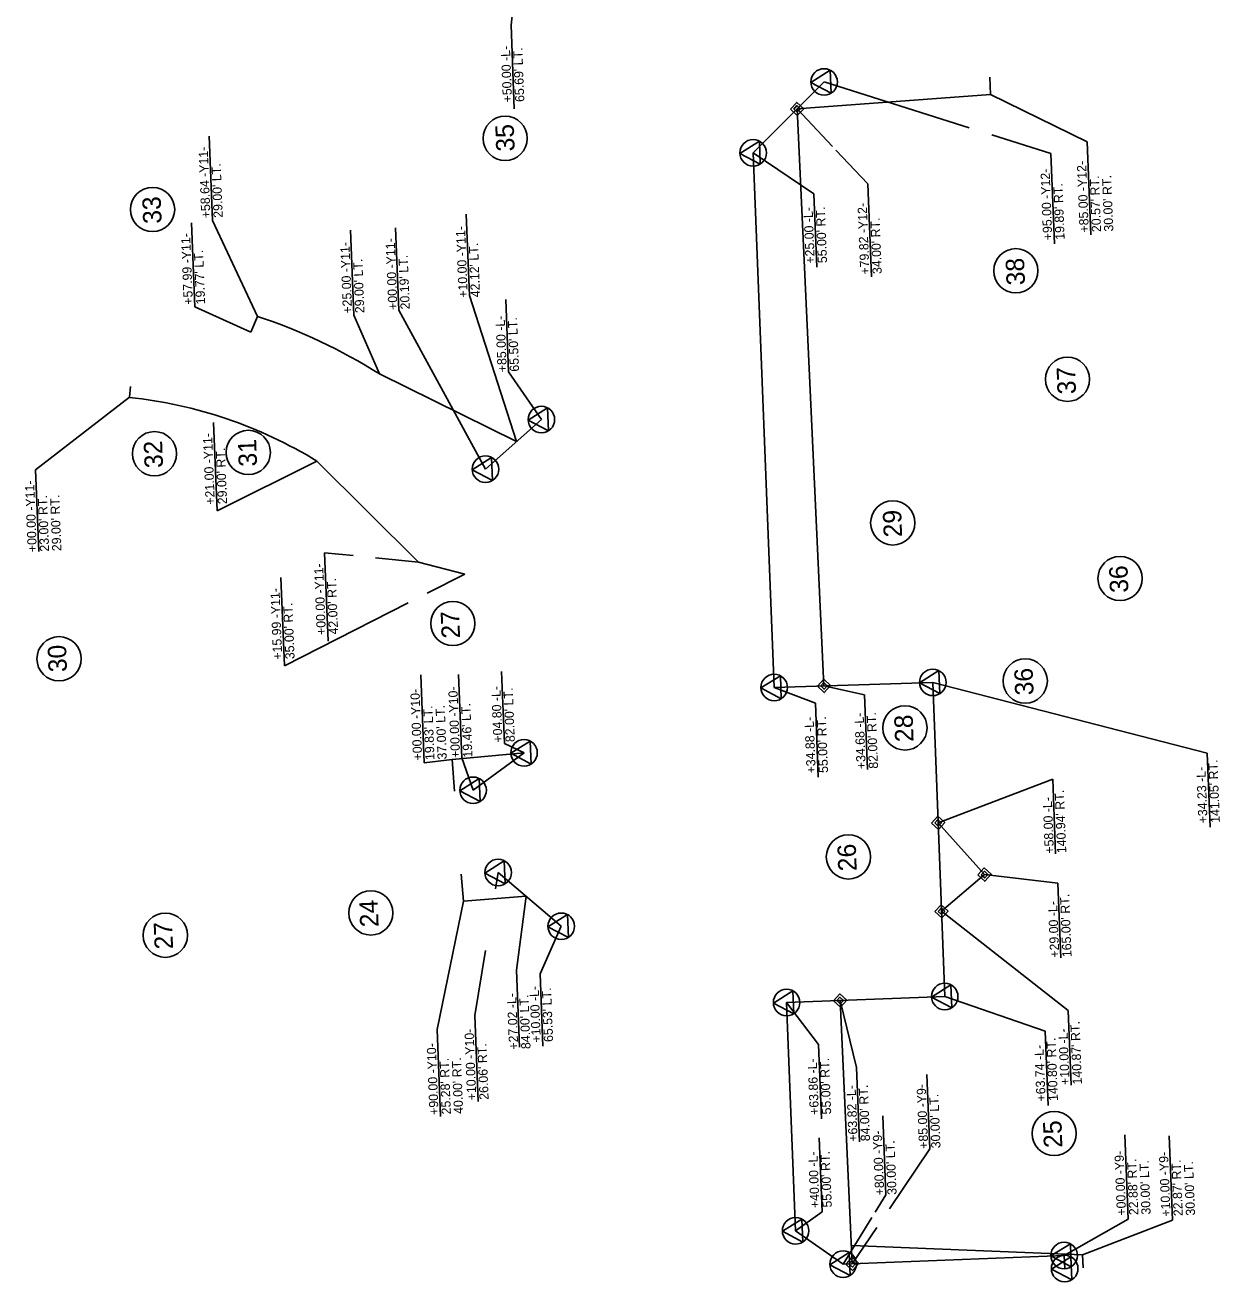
# Model space of a CAD drawing. Extents: x 1627970 to 1628801, y 761752 to 765698.
# Drawn here: x 1628052 to 1628700, y 763889 to 764570 of the extents above; entities that cross this region are included whole.
import ezdxf

# ---------------------------------------------------------------- set-up
doc = ezdxf.new("R2010")
doc.units = 0
for name, color, linetype in [('Exist Property Line Leader', 7, 'Continuous'), ('Exist Property Line Text', 7, 'Continuous'), ('Exist Right of Way Control of Access Line', 7, 'Continuous'), ('Exist Right of Way Easement Line', 7, 'Continuous'), ('Exist Right of Way Monument Leader', 7, 'Continuous'), ('Exist Right of Way Monument Text', 7, 'Continuous'), ('Exist Roads EOT', 7, 'Continuous'), ('Exist Structure Major Deck Tunnel Box Culvert', 7, 'Continuous'), ('Exist Utilities Gas UG Line', 7, 'Continuous'), ('Exist Utilities Gas UG Line Text', 7, 'Continuous'), ('Exist Utilities Other Unknown UG SUE Text', 7, 'Continuous')]:
    doc.layers.add(name, color=color, linetype=linetype)

msp = doc.modelspace()

# ---------------------------------------------------------------- linework, layer by layer
at = {"layer": 'Exist Property Line Leader'}
msp.add_line((1628485.1, 764211.71), (1628470.48, 764524.56), dxfattribs=at)
msp.add_lwpolyline([(1628500.46, 763898.28), (1628493.83, 764041.07)], dxfattribs=at)
at = {"layer": 'Exist Property Line Text'}
for p, q in [((1628312.16, 764508.63), (1628312.16, 764508.63)), ((1628120.93, 764470.04), (1628120.93, 764470.04)), ((1628589.14, 764436.82), (1628589.14, 764436.82)), ((1628617.17, 764377.95), (1628617.17, 764377.95)), ((1628121.94, 764337.62), (1628121.94, 764337.62)), ((1628172.84, 764338.31), (1628172.84, 764338.31)), ((1628522.41, 764300.08), (1628522.41, 764300.08)), ((1628645.68, 764269.95), (1628645.68, 764269.95)), ((1628283.79, 764245.53), (1628283.79, 764245.53)), ((1628070.17, 764226.39), (1628070.17, 764226.39)), ((1628594.27, 764214.35), (1628594.27, 764214.35)), ((1628529.03, 764188.89), (1628529.03, 764188.89)), ((1628498.34, 764118.97), (1628498.34, 764118.97)), ((1628239.29, 764088.56), (1628239.29, 764088.56)), ((1628127.83, 764076.46), (1628127.83, 764076.46)), ((1628609.95, 763968.94), (1628609.95, 763968.94))]:
    msp.add_line(p, q, dxfattribs=at)
for centre in [(1628312.16, 764508.63), (1628120.93, 764470.04), (1628589.14, 764436.82), (1628617.17, 764377.95), (1628121.94, 764337.62), (1628172.84, 764338.31), (1628522.41, 764300.08), (1628645.68, 764269.95), (1628283.79, 764245.53), (1628070.17, 764226.39), (1628594.27, 764214.35), (1628529.03, 764188.89), (1628498.34, 764118.97), (1628239.29, 764088.56), (1628127.83, 764076.46), (1628609.95, 763968.94)]:
    msp.add_circle(centre, 12, dxfattribs=at)
at = {"layer": 'Exist Right of Way Control of Access Line'}
for p, q in [((1628446.68, 764500.75), (1628485.14, 764539.21)), ((1628458.11, 764210.85), (1628446.68, 764500.75)), ((1628301.47, 764329.22), (1628331.79, 764356.11)), ((1628544.12, 764213.6), (1628458.11, 764210.85)), ((1628550.59, 764043.22), (1628544.12, 764213.6)), ((1628294.76, 764155.07), (1628322.4, 764175.4)), ((1628342.59, 764081.32), (1628308.34, 764110.49)), ((1628464.85, 764039.97), (1628550.59, 764043.22)), ((1628469.73, 763916.2), (1628464.85, 764039.97)), ((1628495.46, 763898.08), (1628469.73, 763916.2)), ((1628615.37, 763902.81), (1628495.46, 763898.08)), ((1628615.65, 763895.7), (1628615.37, 763902.81))]:
    msp.add_line(p, q, dxfattribs=at)
at = {"layer": 'Exist Right of Way Easement Line'}
for p, q in [((1628609.15, 764161.03), (1628547.01, 764137.42)), ((1628609.15, 764161.03), (1628610.75, 764120.61)), ((1628612.02, 764104.64), (1628572.2, 764109.39)), ((1628612.02, 764104.64), (1628613.62, 764064.21)), ((1628617.63, 764035.59), (1628548.84, 764089.45)), ((1628617.63, 764035.59), (1628619.23, 763995.17))]:
    msp.add_line(p, q, dxfattribs=at)
at = {"layer": 'Exist Right of Way Monument Leader'}
for points in [[(1628466.89, 764524.41), (1628470.34, 764528.15), (1628474.08, 764524.7), (1628470.63, 764520.96)], [(1628468.69, 764524.49), (1628470.41, 764526.36), (1628472.28, 764524.63), (1628470.56, 764522.76)], [(1628481.5, 764211.57), (1628484.96, 764215.31), (1628488.69, 764211.85), (1628485.24, 764208.11)], [(1628483.3, 764211.64), (1628485.03, 764213.51), (1628486.9, 764211.78), (1628485.17, 764209.91)], [(1628543.42, 764137.28), (1628546.87, 764141.02), (1628550.61, 764137.56), (1628547.16, 764133.82)], [(1628545.21, 764137.35), (1628546.94, 764139.22), (1628548.81, 764137.49), (1628547.08, 764135.62)], [(1628568.6, 764109.25), (1628572.06, 764112.99), (1628575.79, 764109.53), (1628572.34, 764105.79)], [(1628570.4, 764109.32), (1628572.13, 764111.19), (1628574, 764109.46), (1628572.27, 764107.59)], [(1628545.24, 764089.31), (1628548.69, 764093.05), (1628552.43, 764089.6), (1628548.98, 764085.86)], [(1628547.04, 764089.38), (1628548.77, 764091.25), (1628550.63, 764089.52), (1628548.91, 764087.65)], [(1628490.23, 764040.93), (1628493.69, 764044.66), (1628497.43, 764041.21), (1628493.97, 764037.47)], [(1628492.03, 764041), (1628493.76, 764042.87), (1628495.63, 764041.14), (1628493.9, 764039.27)], [(1628496.86, 763898.14), (1628500.32, 763901.88), (1628504.06, 763898.42), (1628500.6, 763894.68)], [(1628498.66, 763898.21), (1628500.39, 763900.08), (1628502.26, 763898.35), (1628500.53, 763896.48)]]:
    msp.add_lwpolyline(points, close=True, dxfattribs=at)
at = {"layer": 'Exist Right of Way Monument Text'}
for p, q in [((1628575.45, 764532.4), (1628575.1, 764541.83)), ((1628470.48, 764524.56), (1628575.45, 764532.4)), ((1628174.24, 764403.55), (1628177.81, 764412.1)), ((1628108.37, 764368.18), (1628109.01, 764374.14)), ((1628243.98, 764380.84), (1628318.33, 764344.17)), ((1628265.07, 764278.8), (1628210.03, 764333.65)), ((1628290.22, 764272.29), (1628265.07, 764278.8)), ((1628283.41, 764171.76), (1628322.4, 764175.4)), ((1628284.77, 764154.64), (1628283.41, 764171.76)), ((1628289.51, 764095), (1628288.34, 764109.68)), ((1628323.47, 764097.6), (1628289.51, 764095)), ((1628625.36, 763903.21), (1628500.13, 763908.27)), ((1628625.64, 763896.08), (1628625.36, 763903.21))]:
    msp.add_line(p, q, dxfattribs=at)
for radius, start, end in [(304, 57.80151, 71.62829), (246, 58.63491, 83.84505)]:
    msp.add_arc((1628081.99, 764123.59), radius, start, end, dxfattribs=at)
at = {"layer": 'Exist Roads EOT'}
for p, q in [((1628470.48, 764524.56), (1628489.77, 764504.12)), ((1628491.57, 764502.22), (1628508.86, 764483.9)), ((1628510.91, 764433.58), (1628508.86, 764483.9)), ((1628507.04, 764206.85), (1628485.1, 764211.71)), ((1628507.04, 764206.85), (1628508.63, 764166.42)), ((1628502.69, 764004.82), (1628493.83, 764041.07)), ((1628502.69, 764004.82), (1628504.28, 763964.4)), ((1628540.92, 764000.99), (1628542.52, 763960.56)), ((1628542.52, 763960.56), (1628520.61, 763928.12)), ((1628513.81, 763918.05), (1628500.46, 763898.28))]:
    msp.add_line(p, q, dxfattribs=at)
at = {"layer": 'Exist Structure Major Deck Tunnel Box Culvert'}
for p, q in [((1628572.2, 764109.39), (1628547.01, 764137.42)), ((1628548.84, 764089.45), (1628572.2, 764109.39))]:
    msp.add_line(p, q, dxfattribs=at)
at = {"layer": 'Exist Utilities Gas UG Line'}
for p, q in [((1628563.83, 764514.39), (1628485.14, 764539.21)), ((1628608.16, 764500.41), (1628576.16, 764510.51)), ((1628479.67, 764478.5), (1628446.68, 764500.75)), ((1628608.16, 764500.41), (1628610.09, 764451.41)), ((1628479.67, 764478.5), (1628481.24, 764438.72)), ((1628252.75, 764460.05), (1628254.51, 764415.5)), ((1628301.47, 764329.22), (1628254.51, 764415.5)), ((1628312.46, 764421.25), (1628314, 764382.03)), ((1628331.79, 764356.11), (1628314, 764382.03)), ((1628286.84, 764217.92), (1628288.63, 764172.7)), ((1628310.22, 764219.41), (1628311.76, 764180.38)), ((1628458.11, 764210.85), (1628480.44, 764202.37)), ((1628544.12, 764213.6), (1628692.97, 764175.3)), ((1628480.44, 764202.37), (1628482.03, 764162.11)), ((1628311.76, 764180.38), (1628322.4, 764175.4)), ((1628288.63, 764172.7), (1628294.76, 764155.07)), ((1628692.97, 764175.3), (1628694.56, 764135.05)), ((1628306.92, 764101.71), (1628308.34, 764110.49)), ((1628331.1, 764055.62), (1628342.59, 764081.32)), ((1628295.73, 764032.92), (1628301.47, 764068.22)), ((1628331.1, 764055.62), (1628332.65, 764016.34)), ((1628550.59, 764043.22), (1628605.14, 764024.48)), ((1628464.85, 764039.97), (1628482.14, 764017.19)), ((1628295.73, 764032.92), (1628297.56, 763986.39)), ((1628605.14, 764024.48), (1628606.72, 763984.22)), ((1628482.14, 764017.19), (1628483.72, 763976.93)), ((1628517.03, 763978.6), (1628518.73, 763935.61)), ((1628482.48, 763966.67), (1628484.07, 763926.42)), ((1628648.29, 763968.19), (1628650.09, 763922.47)), ((1628512.95, 763926.3), (1628518.73, 763935.61)), ((1628469.73, 763916.2), (1628484.07, 763926.42)), ((1628495.46, 763898.08), (1628511.11, 763923.33)), ((1628615.37, 763902.81), (1628650.09, 763922.47))]:
    msp.add_line(p, q, dxfattribs=at)
at = {"layer": 'Exist Utilities Gas UG Line Text'}
for p, q in [((1628321.16, 764620.9), (1628315.34, 764569.97)), ((1628315.34, 764569.97), (1628317.12, 764524.69)), ((1628575.45, 764532.4), (1628627.83, 764506.65)), ((1628151.62, 764509.81), (1628153.42, 764464.15)), ((1628629.88, 764456.34), (1628627.83, 764506.65)), ((1628142.09, 764462.89), (1628143.89, 764417.23)), ((1628177.81, 764412.1), (1628153.42, 764464.15)), ((1628291.01, 764467.44), (1628292.74, 764423.41)), ((1628228.26, 764458.83), (1628230.08, 764412.76)), ((1628292.74, 764423.41), (1628318.33, 764344.17)), ((1628174.24, 764403.55), (1628143.89, 764417.23)), ((1628243.98, 764380.84), (1628230.08, 764412.76)), ((1628108.37, 764368.18), (1628057.44, 764328.89)), ((1628153.97, 764354.62), (1628155.86, 764306.66)), ((1628210.03, 764333.65), (1628155.86, 764306.66)), ((1628057.44, 764328.89), (1628059.18, 764284.59)), ((1628214.22, 764283.9), (1628216.11, 764236)), ((1628229.65, 764282.35), (1628214.22, 764283.9)), ((1628265.07, 764278.8), (1628241.87, 764281.13)), ((1628290.22, 764272.29), (1628269.77, 764261.92)), ((1628190.56, 764270.56), (1628192.45, 764222.66)), ((1628259.59, 764256.75), (1628192.45, 764222.66)), ((1628266.39, 764217.77), (1628268.27, 764170.03)), ((1628268.27, 764170.03), (1628283.41, 764171.76)), ((1628275.32, 764025.35), (1628289.51, 764095)), ((1628318.25, 764057.51), (1628323.47, 764097.6)), ((1628318.25, 764057.51), (1628319.89, 764015.78)), ((1628275.32, 764025.35), (1628277.17, 763978.26)), ((1628672.41, 763967.66), (1628674.21, 763921.94)), ((1628625.36, 763903.21), (1628674.21, 763921.94))]:
    msp.add_line(p, q, dxfattribs=at)
at = {"layer": 'Exist Utilities Other Unknown UG SUE Text'}
for p, q in [((1628485.14, 764539.21), (1628485.14, 764539.21)), ((1628470.48, 764524.56), (1628470.48, 764524.56)), ((1628446.68, 764500.75), (1628446.68, 764500.75)), ((1628331.79, 764356.11), (1628331.79, 764356.11)), ((1628301.47, 764329.22), (1628301.47, 764329.22)), ((1628458.11, 764210.85), (1628458.11, 764210.85)), ((1628485.1, 764211.71), (1628485.1, 764211.71)), ((1628544.12, 764213.6), (1628544.12, 764213.6)), ((1628322.4, 764175.4), (1628322.4, 764175.4)), ((1628294.76, 764155.07), (1628294.76, 764155.07)), ((1628547.01, 764137.42), (1628547.01, 764137.42)), ((1628308.34, 764110.49), (1628308.34, 764110.49)), ((1628572.2, 764109.39), (1628572.2, 764109.39)), ((1628548.84, 764089.45), (1628548.84, 764089.45)), ((1628342.59, 764081.32), (1628342.59, 764081.32)), ((1628493.83, 764041.07), (1628493.83, 764041.07)), ((1628550.59, 764043.22), (1628550.59, 764043.22)), ((1628464.85, 764039.97), (1628464.85, 764039.97)), ((1628469.73, 763916.2), (1628469.73, 763916.2)), ((1628495.46, 763898.08), (1628495.46, 763898.08)), ((1628500.46, 763898.28), (1628500.46, 763898.28)), ((1628615.37, 763902.81), (1628615.37, 763902.81)), ((1628615.65, 763895.7), (1628615.65, 763895.7))]:
    msp.add_line(p, q, dxfattribs=at)
for points in [[(1628477.93, 764538.94), (1628488.5, 764545.58), (1628488.99, 764533.11)], [(1628439.47, 764500.48), (1628450.04, 764507.12), (1628450.53, 764494.65)], [(1628324.58, 764355.84), (1628335.14, 764362.48), (1628335.64, 764350.01)], [(1628294.26, 764328.95), (1628304.82, 764335.59), (1628305.32, 764323.12)], [(1628536.91, 764213.33), (1628547.48, 764219.97), (1628547.97, 764207.5)], [(1628450.9, 764210.58), (1628461.47, 764217.22), (1628461.96, 764204.75)], [(1628315.2, 764175.13), (1628325.76, 764181.77), (1628326.25, 764169.3)], [(1628287.56, 764154.8), (1628298.12, 764161.44), (1628298.61, 764148.97)], [(1628301.13, 764110.22), (1628311.7, 764116.85), (1628312.19, 764104.39)], [(1628335.38, 764081.05), (1628345.95, 764087.69), (1628346.44, 764075.22)], [(1628543.39, 764042.95), (1628553.95, 764049.59), (1628554.44, 764037.13)], [(1628457.64, 764039.7), (1628468.21, 764046.33), (1628468.7, 764033.87)], [(1628462.52, 763915.93), (1628473.09, 763922.57), (1628473.58, 763910.1)], [(1628488.26, 763897.81), (1628498.82, 763904.45), (1628499.31, 763891.98)], [(1628608.16, 763902.54), (1628618.73, 763909.18), (1628619.22, 763896.71)], [(1628608.44, 763895.43), (1628619.01, 763902.07), (1628619.5, 763889.6)]]:
    msp.add_lwpolyline(points, close=True, dxfattribs=at)
for centre in [(1628485.14, 764539.21), (1628446.68, 764500.75), (1628331.79, 764356.11), (1628301.47, 764329.22), (1628458.11, 764210.85), (1628544.12, 764213.6), (1628322.4, 764175.4), (1628294.76, 764155.07), (1628308.34, 764110.49), (1628342.59, 764081.32), (1628464.85, 764039.97), (1628550.59, 764043.22), (1628469.73, 763916.2), (1628495.46, 763898.08), (1628615.37, 763902.81), (1628615.65, 763895.7)]:
    msp.add_circle(centre, 7.2, dxfattribs=at)

# ---------------------------------------------------------------- texts
at = {"layer": 'Exist Property Line Text'}
for s, p in [('35', (1628317.35, 764501.67)), ('33', (1628125.85, 764462.48)), ('38', (1628594.16, 764429.11)), ('37', (1628621.82, 764370.01)), ('32', (1628126.63, 764330.01)), ('31', (1628177.64, 764330.8)), ('29', (1628527.51, 764292.48)), ('36', (1628650.25, 764262.35)), ('27', (1628287.73, 764237.62)), ('30', (1628074.54, 764219.31)), ('36', (1628598.83, 764206.75)), ('28', (1628533.72, 764181.43)), ('26', (1628502.88, 764111.4)), ('24', (1628243.54, 764081.04)), ('27', (1628132.06, 764069.02)), ('25', (1628614.43, 763961.35))]:
    msp.add_text(s, height=10, rotation=92.25819, dxfattribs=at).set_placement(p)
at = {"layer": 'Exist Right of Way Easement Line'}
for s, p in [('+58.00 -L-', (1628609.9, 764120.82)), ("140.94' RT.", (1628616.56, 764121.08)), ('+29.00 -L-', (1628612.77, 764064.42)), ("165.00' RT.", (1628619.43, 764064.69)), ("140.87' RT.", (1628625.04, 763995.64)), ('+10.00 -L-', (1628618.38, 763995.37))]:
    msp.add_text(s, height=5, rotation=92.25819, dxfattribs=at).set_placement(p)
at = {"layer": 'Exist Roads EOT'}
for s, p in [('+79.82 -Y12-', (1628509.79, 764434.88)), ("34.00' RT.", (1628516.46, 764435.15)), ('+34.68 -L-', (1628507.79, 764166.63)), ("82.00' RT.", (1628514.45, 764166.89)), ('+63.82 -L-', (1628503.44, 763964.61)), ("84.00' RT.", (1628510.1, 763964.87)), ('+85.00 -Y9-', (1628541.67, 763960.77)), ("30.00' LT.", (1628548.33, 763961.03))]:
    msp.add_text(s, height=5, rotation=92.25819, dxfattribs=at).set_placement(p)
at = {"layer": 'Exist Utilities Gas UG Line'}
for s, p in [('+95.00 -Y12-', (1628608.99, 764453.47)), ("19.89' RT.", (1628615.65, 764453.74)), ('+25.00 -L-', (1628480.13, 764440.79)), ("55.00' RT.", (1628486.79, 764441.05)), ('+00.00 -Y11-', (1628253.78, 764415.71)), ("20.19' LT.", (1628260.44, 764415.97)), ('+85.00 -L-', (1628313.08, 764381.91)), ("65.50' LT.", (1628319.74, 764382.18)), ('+00.00 -Y10-', (1628287.76, 764172.65)), ('+04.80 -L-', (1628310.77, 764181.07)), ("82.00' LT.", (1628317.43, 764181.33)), ("19.46' LT.", (1628294.42, 764172.92)), ('+34.88 -L-', (1628480.67, 764164.32)), ("55.00' RT.", (1628487.33, 764164.58)), ("141.05' RT.", (1628699.86, 764137.51)), ('+34.23 -L-', (1628693.19, 764137.25)), ('+10.00 -L-', (1628331.54, 764018.4)), ("65.53' LT.", (1628338.21, 764018.67)), ('+10.00 -Y10-', (1628296.55, 763987.08)), ("140.80' RT.", (1628612.02, 763986.69)), ("26.06' RT.", (1628303.21, 763987.34)), ('+63.74 -L-', (1628605.36, 763986.43)), ('+63.86 -L-', (1628482.36, 763979.14)), ("55.00' RT.", (1628489.02, 763979.4)), ('+80.00 -Y9-', (1628517.85, 763935.52)), ('+40.00 -L-', (1628482.7, 763928.62)), ("55.00' RT.", (1628489.37, 763928.89)), ("30.00' LT.", (1628524.51, 763935.78)), ('+00.00 -Y9-', (1628648.98, 763924.53)), ("22.88' RT.", (1628655.65, 763924.79)), ("30.00' LT.", (1628662.31, 763925.06))]:
    msp.add_text(s, height=5, rotation=92.25819, dxfattribs=at).set_placement(p)
at = {"layer": 'Exist Utilities Gas UG Line Text'}
for s, p in [('+50.00 -L-', (1628315.94, 764528.2)), ("65.69' LT.", (1628322.6, 764528.47)), ('+58.64 -Y11-', (1628152.34, 764465.4)), ("29.00' LT.", (1628159.01, 764465.66)), ('+85.00 -Y12-', (1628628.76, 764457.64)), ("20.57' RT.", (1628635.42, 764457.9)), ("30.00' RT.", (1628642.09, 764458.16)), ('+57.99 -Y11-', (1628142.81, 764418.48)), ('+10.00 -Y11-', (1628291.92, 764422.29)), ('+25.00 -Y11-', (1628229.18, 764413.67)), ("42.12' LT.", (1628298.59, 764422.55)), ("19.77' LT.", (1628149.47, 764418.74)), ("29.00' LT.", (1628235.84, 764413.94)), ('+21.00 -Y11-', (1628154.7, 764310.07)), ("29.00' RT.", (1628161.36, 764310.33)), ('+00.00 -Y11-', (1628058.17, 764284.34)), ("23.00' RT.", (1628064.83, 764284.6)), ("29.00' RT.", (1628071.49, 764284.87)), ('+00.00 -Y11-', (1628214.95, 764239.41)), ("42.00' RT.", (1628221.61, 764239.67)), ('+15.99 -Y11-', (1628191.29, 764226.01)), ("35.00' RT.", (1628197.95, 764226.27)), ('+00.00 -Y10-', (1628267.19, 764171.36)), ("19.83' LT.", (1628273.86, 764171.62)), ("37.00' LT.", (1628280.52, 764171.88)), ('+27.02 -L-', (1628319.28, 764014.57)), ("84.00' LT.", (1628325.94, 764014.84)), ('+90.00 -Y10-', (1628276.09, 763979.16)), ("25.28' RT.", (1628282.75, 763979.42)), ("40.00' RT.", (1628289.41, 763979.68)), ('+10.00 -Y9-', (1628673.1, 763924)), ("22.87' RT.", (1628679.76, 763924.26)), ("30.00' LT.", (1628686.43, 763924.53))]:
    msp.add_text(s, height=5, rotation=92.25819, dxfattribs=at).set_placement(p)

doc.saveas('drawing.dxf')
